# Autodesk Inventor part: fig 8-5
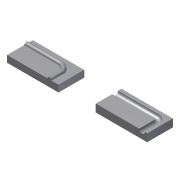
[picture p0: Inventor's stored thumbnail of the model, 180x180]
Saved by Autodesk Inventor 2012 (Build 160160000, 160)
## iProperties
Created: 2009-04
Part Number: fig 8-5
Document SubType Name: Modeling
Designer: Sham
Density: 1 g/cm^3
Material: Default
Author: Sham
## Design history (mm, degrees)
sketch "Sketch1"
  geometry: L1 (-20, 20)-(20, 20); L2 (20, 20)-(20, 0); L3 (20, 0)-(-20, 0); L4 (-20, 0)-(-20, 20); L5 (-88, 19)-(-48, 19); L6 (-48, 19)-(-48, -1); L7 (-48, -1)-(-88, -1); L8 (-88, -1)-(-88, 19)
  constraints: 16 end point
extrude "Extrusion1" new body sketch "Sketch1" distance "d0" = 6; taper "d1" = 0 deg
sketch "Sketch4"
  geometry: L1 (6, 0)-(6, 20) reference; C1 r 2.236 at (6, 15)
  constraints: 1 centre point, 1 point on line
sketch "Sketch5"
  geometry: L1 (-20, 0)-(-20, 20) reference; L2 (20, 0)-(-20, 0) reference; L3 (-20, 15)-(11.667, 15); L4 (16, 10.667)-(16, 0); A1 r 4.333 centre (11.667, 10.667) between (16, 10.667) and (11.667, 15)
  constraints: 4 end point, 2 point on circle, 2 point on line, 1 centre point, 1 tangent
sweep "Sweep5" sketch "Sketch4", "Sketch5" dims "d6" = 0
extrude "Extrusion2" join sketch "Sketch1" distance "d7" = 5.25; taper "d8" = 0 deg
sketch "Sketch6"
  geometry: L1 (-88, -1)-(-88, 19) reference; L2 (-48, -1)-(-88, -1) reference; L3 (-88, 14)-(-62, 14); L4 (-55, 9)-(-55, -1); A1 r 7.4 centre (-62, 6.6) between (-55, 9) and (-62, 14); 1 further point
  constraints: 4 end point, 2 point on circle, 2 point on line, 1 centre point, 1 parallel, 1 perpendicular, 1 tangent
sketch "Sketch7"
  geometry: L1 (5.25, 0)-(5.25, 20) reference; C1 r 1.601 at (5.25, 15); 1 further point
  constraints: 1 centre point, 1 point on line
sweep "Sweep6" sketch "Sketch6", "Sketch7" dims "d9" = 0
body "Solid1"
